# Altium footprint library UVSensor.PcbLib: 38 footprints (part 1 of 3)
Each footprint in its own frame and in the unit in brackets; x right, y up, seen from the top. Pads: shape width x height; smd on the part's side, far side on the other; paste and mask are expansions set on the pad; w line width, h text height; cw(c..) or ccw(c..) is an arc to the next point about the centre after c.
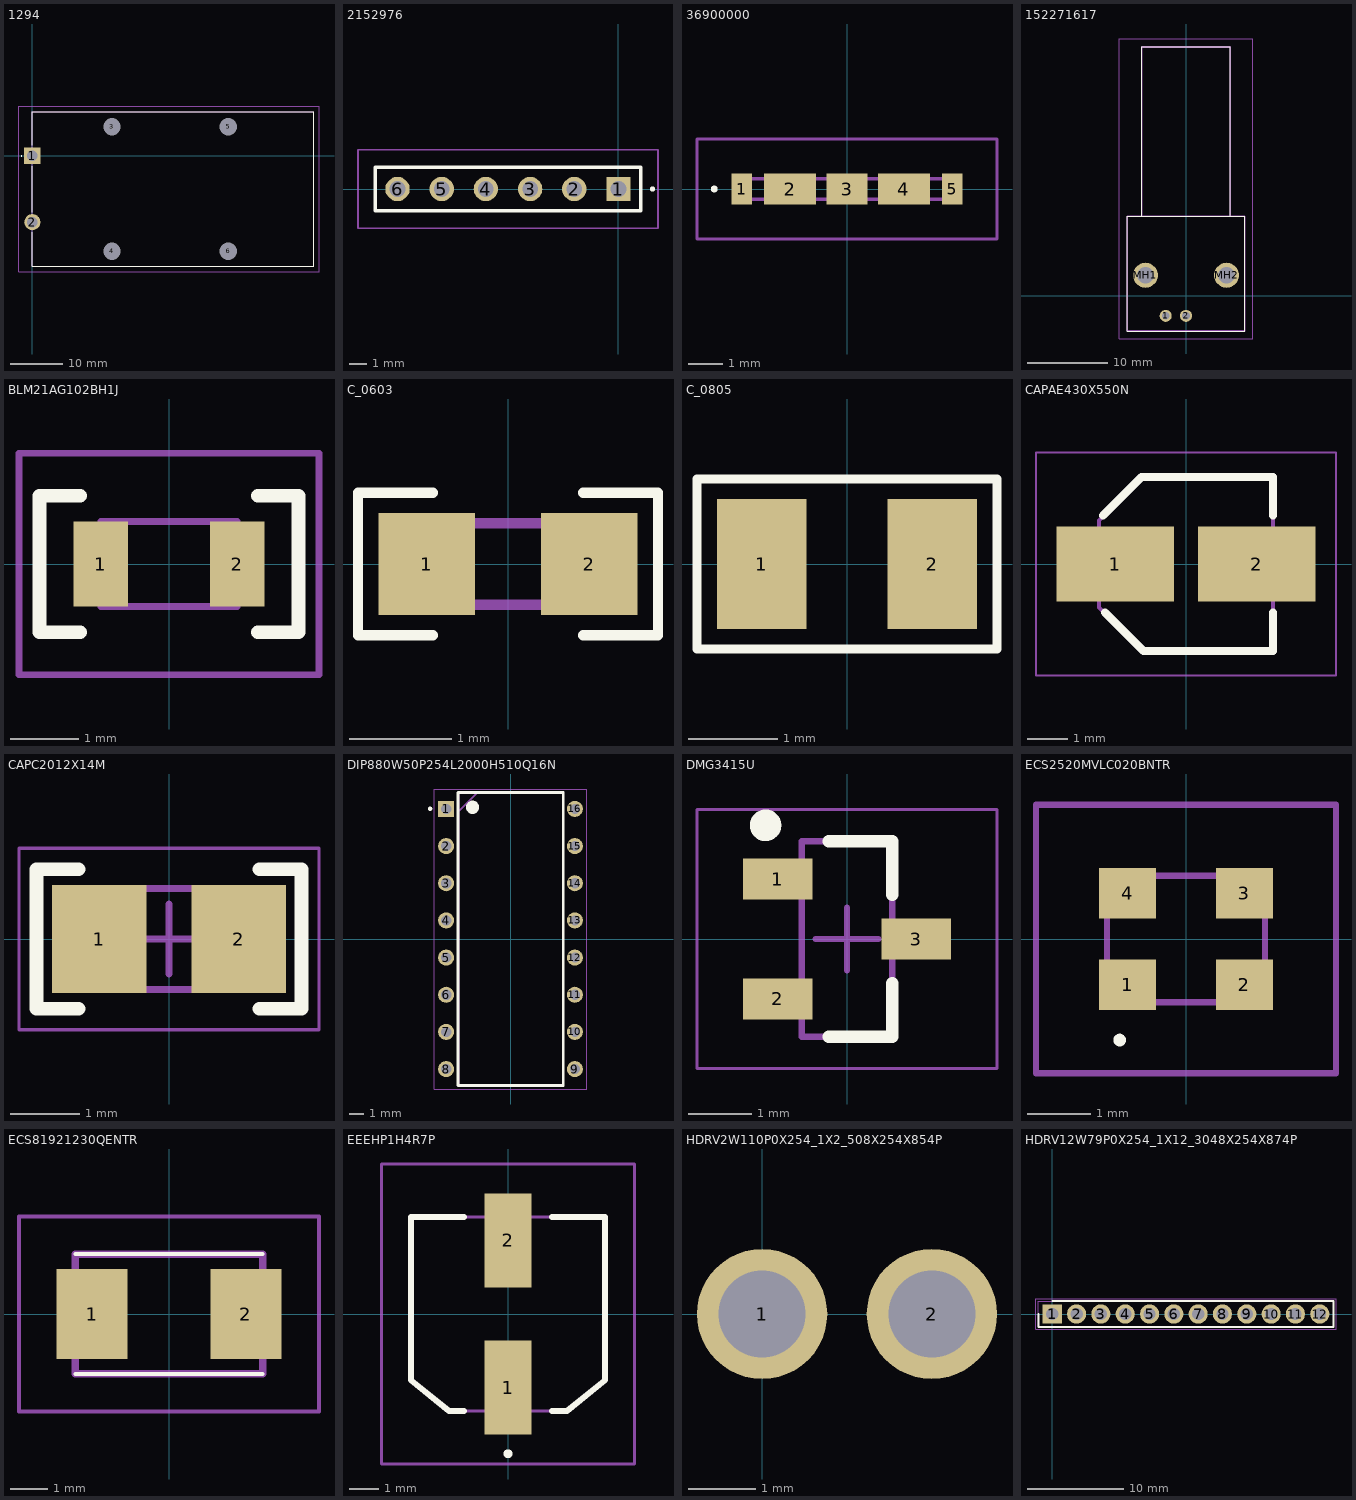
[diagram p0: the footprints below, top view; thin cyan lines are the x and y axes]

## 1294 [mm]
pads (6):
  rect 3.09x3.09 hole 2.06: 1(0,0)
  round 3.09 hole 2.06: 2(0,-12.7)
  round 1.65 hole 3.3 unplated: 3(15.24,5.565) 4(15.24,-18.265) 5(37.47,5.565) 6(37.47,-18.265)
Top Overlay:
  lines w0.1: -2.1,0 ccw(c-2.05,0) -2,0 ccw(c-2.05,0) -2.1,0
  lines w0.2: 0,-14.6 0,-21.135 53.85,-21.135 53.85,8.435 0,8.4 0,2 ; 0,-10.8 0,-2
Mechanical 13:
  text ".Designator" at 6.394,9.702 h2
Mechanical 15:
  lines w0.1: 0,-21.135 0,8.435 53.85,8.435 53.85,-21.135 0,-21.135
Mechanical 20:
  lines w0.1: -2.545,-22.135 -2.545,9.435 54.85,9.435 54.85,-22.135 -2.545,-22.135
3D body "1294.stp": height 20.32, standoff -7.62, extent -0.305,-21.133 53.848,8.433

## 2152976 [mm]
pads (6):
  rect 1.4x1.4 hole 0.9: 1(0,0)
  round 1.4 hole 0.9: 2(-2.54,0) 3(-5.08,0) 4(-7.62,0) 5(-10.16,0) 6(-12.7,0)
Top Overlay:
  lines w0.2: 1.9,0 cw(c1.95,0) 2,0 ; 1.9,0 ccw(c1.95,0) 2,0 ; 1.9,0 cw(c1.95,0) 2,0 ; -13.97,-1.26 -13.97,1.26 1.27,1.26 1.27,-1.26 -13.97,-1.26
Mechanical 13:
  lines w0.1: -13.97,-1.26 1.27,-1.26 1.27,1.26 -13.97,1.26 -13.97,-1.26
  text ".Designator" at -12.573,0.381 h0.76
Mechanical 15:
  lines w0.1: -14.97,-2.26 -14.97,2.26 2.27,2.26 2.27,-2.26 -14.97,-2.26
3D body "215297-6.stp": height 7.2, standoff -5, extent -13.97,-1.26 1.27,1.26

## 36900000 [mm]
pads (5):
  rect 0.6x0.9 smd: 1(-3.05,0) 5(3.05,0)
  rect 1.5x0.9 smd: 2(-1.65,0) 4(1.65,0)
  rect 1.2x0.9 smd: 3(0,0)
Top Overlay:
  lines w0.1: -3.9,0 cw(c-3.85,0) -3.8,0 cw(c-3.85,0) -3.9,0
Mechanical 13:
  lines w0.1: -2.95,-0.3 -2.95,0.3 2.95,0.3 2.95,-0.3 -2.95,-0.3
  text ".Designator" at -3.3,0.867 h0.5
Mechanical 15:
  lines w0.1: -4.35,-1.45 -4.35,1.45 4.35,1.45 4.35,-1.45 -4.35,-1.45
3D body "36900000.stp": height 1.28, standoff 0, extent -3.25,-0.41 3.25,0.41

## 152271617 [mm]
pads (4):
  round 1.509 hole 0.97: 1(-2.54,-2.54) 2(0,-2.54)
  round 3.135 hole 2.09: MH1(-5.08,2.54) MH2(5.08,2.54)
Top Overlay:
  lines w0.1: -5.535,9.91 -5.535,31.12 5.535,31.12 5.535,9.91 ; -7.38,-4.44 7.38,-4.44 7.38,9.91 -7.38,9.91 -7.38,-4.44
Mechanical 13:
  lines w0.2: -5.535,9.91 -5.535,31.12 5.535,31.12 5.535,9.91 ; -7.38,-4.44 7.38,-4.44 7.38,9.91 -7.38,9.91 -7.38,-4.44
Mechanical 15:
  lines w0.1: -8.38,-5.44 8.38,-5.44 8.38,32.12 -8.38,32.12 -8.38,-5.44
3D body "1-5227161-7.stp": height 15.84, standoff -3.12, extent -8.139,-3.845 8.139,31.08

## BLM21AG102BH1J [mm]
pads (2):
  rect 0.8x1.25 smd: 1(-1,0) 2(1,0)
Top Overlay:
  lines w0.2: -1.3,-1 -1.9,-1 -1.9,1 -1.3,1 ; 1.3,-1 1.9,-1 1.9,1 1.3,1
Mechanical 13:
  lines w0.1: -1,-0.625 -1,0.625 1,0.625 1,-0.625 -1,-0.625
  text ".Designator" at -1.78,1.257 h0.5
Mechanical 15:
  lines w0.1: -2.2,-1.625 -2.2,1.625 2.2,1.625 2.2,-1.625 -2.2,-1.625
3D body "BLM21SP601BH1D.stp": height 0.85, standoff 0, extent -1,-0.625 1,0.625

## C_0603 [mm]
pads (2):
  rect 0.95x1 smd: 1(-0.8,0) 2(0.8,0)
Top Overlay:
  lines w0.1: -0.738,-0.7 -1.475,-0.7 -1.475,0.7 -0.738,0.7 ; 0.737,-0.7 1.475,-0.7 1.475,0.7 0.737,0.7
Mechanical 13:
  lines w0.1: -0.8,-0.4 0.8,-0.4 0.8,0.4 -0.8,0.4 -0.8,-0.4
  text ".Designator" at -1.475,0.986 h1.52
3D body "C0603.stp": height 0.81, standoff 0.01, extent -0.8,-0.4 0.8,0.4

## C_0805 [mm]
pads (2):
  rect 1x1.45 smd: 1(-0.95,0) 2(0.95,0)
Top Overlay:
  lines w0.1: -1.675,-0.95 -1.675,0.95 1.675,0.95 1.675,-0.95 -1.675,-0.95
Mechanical 13:
  text ".Designator" at -0.073,0.706 h0.76
3D body "C0805.stp": height 1.26, standoff 0.01, extent -1,-0.625 1,0.625

## CAPAE430X550N [mm]
pads (2):
  rect 2.9x1.85 smd: 1(-1.75,0) 2(1.75,0)
Top Overlay:
  lines w0.2: -2.05,1.2 -1.1,2.15 2.15,2.15 2.15,1.2 ; -2,-1.2 -1.05,-2.15 2.15,-2.15 2.15,-1.2
Mechanical 13:
  lines w0.1: -2.15,-1.075 -1.075,-2.15 2.15,-2.15 2.15,2.15 -1.075,2.15 -2.15,1.075 -2.15,-1.075
  text ".Designator" at -0.498,1.331 h0.76
Mechanical 15:
  lines w0.05: -3.7,-2.75 -3.7,2.75 3.7,2.75 3.7,-2.75 -3.7,-2.75
3D body "UWP1HR33MCL1GB.stp": height 5.5, standoff 0, extent -2.5,-2.25 2.5,2.25

## CAPC2012X14M [mm] "Capacitor, 0805 (2012 metric), 2.0x1.25x1.4mm, Kemet"
height 1.4
pads (2):
  rect 1.35x1.55 smd: 1(-1,0) 2(1,0)
Top Overlay:
  lines w0.2: -1.3,-1 -1.9,-1 -1.9,1 -1.3,1 ; 1.3,-1 1.9,-1 1.9,1 1.3,1
Mechanical 13:
  lines w0.1: -1.1,-0.725 -1.1,0.725 1.1,0.725 1.1,-0.725 -1.1,-0.725
  text ".Designator" at -2.75,1.5 h1.52
Mechanical 15:
  lines w0.05: -2.15,-1.3 -2.15,1.3 2.15,1.3 2.15,-1.3 -2.15,-1.3
  lines w0.1: -0.5,0 0.5,0 ; 0,-0.5 0,0.5
3D body "CAPC2012X14M.step": height 1.4, standoff 0, extent -1.1,-0.725 1.1,0.725

## DIP880W50P254L2000H510Q16N [mm]
pads (16):
  rect 1.1x1.1 hole 0.7: 1(-4.4,8.89)
  round 1.1 hole 0.7: 2(-4.4,6.35) 3(-4.4,3.81) 4(-4.4,1.27) 5(-4.4,-1.27) 6(-4.4,-3.81) 7(-4.4,-6.35) 8(-4.4,-8.89) 9(4.4,-8.89) 10(4.4,-6.35) 11(4.4,-3.81) 12(4.4,-1.27) 13(4.4,1.27) 14(4.4,3.81) 15(4.4,6.35) 16(4.4,8.89)
Top Overlay:
  lines w0.2: -5.55,8.9 ccw(c-5.5,8.9) -5.45,8.9 ; -5.55,8.9 cw(c-5.5,8.9) -5.45,8.9 ; -5.55,8.9 ccw(c-5.5,8.9) -5.45,8.9 ; -3.6,-10 3.6,-10 3.6,10 -3.6,10 -3.6,-10
  lines w0.5: -2.8,9 cw(c-2.6,9) -2.4,9 cw(c-2.6,9) -2.8,9
Mechanical 13:
  lines w0.1: -3.55,8.73 -2.28,10 ; -3.55,-10 -3.55,10 3.55,10 3.55,-10 -3.55,-10
  text ".Designator" at -3.6,10.688 h1
Mechanical 15:
  lines w0.05: -5.2,-10.25 -5.2,10.25 5.2,10.25 5.2,-10.25 -5.2,-10.25
3D body "ULN2064B.stp": height 5.1, standoff -3.5, extent -4.525,-10 4.525,10

## DMG3415U [mm]
pads (3):
  rect 1.1x0.65 smd: 1(-1.1,0.95) 2(-1.1,-0.95) 3(1.1,0)
Top Overlay:
  circle w0.25: c-1.29,1.8 r0.125
  lines w0.2: -0.285,-1.55 0.715,-1.55 0.715,-0.7 ; -0.285,1.55 0.715,1.55 0.715,0.7
Mechanical 13:
  lines w0.1: -0.715,-1.55 0.715,-1.55 0.715,1.55 -0.715,1.55 -0.715,-1.55
  text ".Designator" at -3.175,2.032 h1.52
Mechanical 15:
  lines w0.05: -2.375,-2.05 2.375,-2.05 2.375,2.05 -2.375,2.05 -2.375,-2.05
  lines w0.1: -0.5,0 0.5,0 ; 0,-0.5 0,0.5
3D body "SOT95P248X115-3M.step": height 1.15, standoff 0, extent -1.3,-1.55 1.3,1.55

## ECS2520MVLC020BNTR [mm]
pads (4):
  rect 0.9x0.8 smd: 1(-0.925,-0.725) 2(0.925,-0.725) 3(0.925,0.725) 4(-0.925,0.725)
Top Overlay:
  lines w0.1: -1.1,-1.6 ccw(c-1.05,-1.6) -1,-1.6 ccw(c-1.05,-1.6) -1.1,-1.6
Mechanical 13:
  lines w0.1: -1.25,-1 -1.25,1 1.25,1 1.25,-1 -1.25,-1
  text ".Designator" at -1.094,-1.638 h0.5
Mechanical 15:
  lines w0.1: -2.375,-2.125 -2.375,2.125 2.375,2.125 2.375,-2.125 -2.375,-2.125
3D body "ECS-2520MVLC-020-BN-TR.stp": height 1, standoff 0, extent -1.295,-1.045 1.295,1.045

## ECS81921230QENTR [mm]
pads (2):
  rect 1.9x2.4 smd: 1(-2.05,0) 2(2.05,0)
Top Overlay:
  lines w0.1: -2.5,-1.6 2.5,-1.6 ; -2.5,1.6 2.5,1.6
Mechanical 13:
  lines w0.2: -2.5,-1.6 -2.5,1.6 2.5,1.6 2.5,-1.6 -2.5,-1.6
  text ".Designator" at -2.4,1.867 h0.5
Mechanical 15:
  lines w0.1: -4,-2.6 -4,2.6 4,2.6 4,-2.6 -4,-2.6
3D body "ECS-81.92-12-30Q-EN-TR.stp": height 1.1, standoff 0, extent -2.54,-1.6 2.5,1.6

## EEEHP1H4R7P [mm]
pads (2):
  rect 1.6x3.2 smd: 1(0,-2.5) 2(0,2.5)
Top Overlay:
  lines w0.2: -1.5,-3.3 -2,-3.3 -3.3,-2.25 -3.3,3.3 -1.5,3.3 ; 1.5,-3.3 2,-3.3 3.3,-2.25 3.3,3.3 1.5,3.3 ; 0,-4.8 ccw(c0,-4.75) 0,-4.7 ; 0,-4.8 cw(c0,-4.75) 0,-4.7 ; 0,-4.8 ccw(c0,-4.75) 0,-4.7
Mechanical 13:
  lines w0.1: -2,-3.3 -3.3,-2.25 -3.3,3.3 3.3,3.3 3.3,-2.25 2,-3.3 ; -2,-3.3 2,-3.3 ; -2,-3.3 2,-3.3
  text ".Designator" at -0.073,-0.044 h0.76
Mechanical 15:
  lines w0.1: -4.3,-5.1 -4.3,5.1 4.3,5.1 4.3,-5.1 -4.3,-5.1
3D body "EEE-FH1V100XL.stp": height 7.7, standoff 0, extent -3.3,-3.65 3.3,3.65

## HDRV2W110P0X254_1X2_508X254X854P [mm]
pads (2):
  round 1.95 hole 1.3: 1(0,0) 2(2.54,0)
Mechanical 13:
  text ".Designator" at -1.245,1.612 h0.5

## HDRV12W79P0X254_1X12_3048X254X874P [mm]
pads (12):
  rect 2x2 hole 1.3: 1(0,0)
  round 2 hole 1.3: 2(2.54,0) 3(5.08,0) 4(7.62,0) 5(10.16,0) 6(12.7,0) 7(15.24,0) 8(17.78,0) 9(20.32,0) 10(22.86,0) 11(25.4,0) 12(27.94,0)
Top Overlay:
  lines w0.2: -1.445,0 -1.445,-1.345 29.385,-1.345 29.385,1.345 0,1.345
Mechanical 13:
  lines w0.1: -1.445,-1.345 -1.445,1.345 29.385,1.345 29.385,-1.345 -1.445,-1.345
  text ".Designator" at -1.345,1.612 h0.5
Mechanical 15:
  lines w0.05: -1.695,-1.595 -1.695,1.595 29.635,1.595 29.635,-1.595 -1.695,-1.595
